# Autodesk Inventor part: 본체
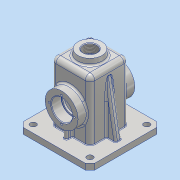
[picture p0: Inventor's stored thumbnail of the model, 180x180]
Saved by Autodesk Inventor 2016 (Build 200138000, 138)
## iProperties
Created: 2018-10
Part Number: 본체
Material: 알루미늄 6061
Document SubType Name: Modeling
Designer: user
Density: 2.7 g/cm^3
Appearance: 알루미늄 - 평지
Mass: 794.227 g
Surface Area: 899.5 cm^2
Volume: 294.158 cm^3
Author: user
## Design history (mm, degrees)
sketch "스케치1"
  geometry: L1 (-52, -60)-(52, -60); L2 (60, -52)-(60, 52); L3 (52, 60)-(-52, 60); L4 (-60, 52)-(-60, -52); L5 (-60, -60)-(60, 60); L6 (60, -60)-(-60, 60); L7 (-60, 52)-(-52, 60); L8 (52, 60)-(60, 52); L9 (60, -52)-(52, -60); L10 (-52, -60)-(-60, -52); 1 further point
  constraints: 20 end point, 8 point on line, 2 midpoint, 2 parallel, 1 horizontal, 1 perpendicular
  dimensions: "d0" = 120 distance of L5.start L6.start; "d1" = 120 distance of L5.end L6.start; "d2" = 8 distance of L4.start L6.end; "d3" = 8 distance of L3.end L6.end (= d2); "d4" = 8 distance of L3.start L5.end (= d2); "d5" = 8 distance of L2.end L5.end (= d4); "d6" = 8 distance of L2.start L6.start (= d2); "d7" = 8 distance of L1.end L6.start (= d6); "d8" = 8 distance of L1.start L5.start (= d2); "d9" = 8 distance of L4.end L5.start (= d8)
extrude "돌출1" new body sketch "스케치1" distance "d10" = 10; taper "d11" = 0 deg
sketch "스케치2"
  geometry: L1 (-32.5, 32.5)-(32.5, 32.5); L2 (32.5, 32.5)-(32.5, -32.5); L3 (32.5, -32.5)-(-32.5, -32.5); L4 (-32.5, -32.5)-(-32.5, 32.5); L5 (-32.5, 32.5)-(32.5, -32.5); L6 (32.5, 32.5)-(-32.5, -32.5); 1 further point
  constraints: 12 end point, 2 midpoint, 2 parallel, 1 horizontal, 1 perpendicular
  dimensions: "d12" = 65 distance of L1.start L1.end; "d13" = 65 distance of L1.end L2.end
extrude "돌출2" join sketch "스케치2" distance "d14" = 100; taper "d15" = 0 deg
node "작업 평면1"
fillet "모깎기1" dims "d17" = 8
fillet "모깎기2" dims "d18" = 8
feature "쉘1" dims "d19" = 10, "d20" = 5
sketch "스케치3"
  geometry: C1 r 20 at (0, 0); 1 further point
  constraints: 1 centre point, 1 coincident
  dimensions: "d21" = 40 diameter of C1
extrude "돌출3" join sketch "스케치3" stored distance "d22" = 100; taper "d23" = 7 deg
hole "구멍1" diameter "d26" = 22.835; stored, may be unused: countersink angle "d30" = 90 deg, drill point angle "d32" = 118 deg; dims "d24" = 10, "d25" = 10, "d27" = 50, "d28" = 4, "d29" = 2, "d31" = 59.3
sketch "스케치6"
  geometry: L1 (76.5, -10)-(-27.5, -10) reference; C1 r 27.5 at (24.5, 45); 2 further points
  constraints: 1 centre point, 1 midpoint, 1 vertical alignment
  dimensions: "d33" = 55 diameter of C1; "d34" = 55 distance from line of L1 C1.centre
extrude "돌출4" join sketch "스케치6" distance "d35" = 15; taper "d37" = 0 deg; dims "d36" = 2, "d38" = 0
hole "구멍2" diameter "d41" = 30; stored, may be unused: countersink angle "d45" = 90 deg, drill point angle "d47" = 118 deg; dims "d39" = 10, "d40" = 10, "d42" = 17, "d43" = 35, "d44" = 17, "d46" = 59.3
sketch "스케치7"
  geometry: C1 r 15 at (0, 0) reference; 2 further points
  constraints: 1 vertical alignment
  dimensions: "d48" = 21 distance of C1.centre point (0, 21)
hole "구멍3" sketch "스케치7" at (0, 21) diameter "d49" = 3.242; stored, may be unused: countersink angle "d53" = 90 deg, drill point angle "d55" = 118 deg; dims "d50" = 8, "d51" = 35, "d52" = 17, "d54" = 10
sketch "스케치8"
  geometry: L1 (-32.5, 27.5)-(-47.5, 27.5) reference; L2 (-42.5, 27.5)-(-42.5, 9.287); L3 (20, 120)-(21.228, 110) reference; L4 (21.228, 110)-(24.5, 110) reference; L5 (32.5, 102)-(32.5, 82.5) reference; L6 (32.5, 82.5)-(47.5, 82.5) reference; L7 (47.5, 82.5)-(47.5, 77.621) reference; L8 (47.5, 77.621)-(37.5, 77.621) reference; L9 (37.5, 77.621)-(36.526, 76) reference; L10 (36.526, 76)-(37.5, 74.379) reference; L11 (37.5, 74.379)-(47.5, 74.379) reference; L12 (47.5, 74.379)-(47.5, 72.5) reference; L13 (47.5, 72.5)-(30.5, 72.5) reference; L14 (30.5, 72.5)-(30.5, 70) reference; L15 (30.5, 70)-(27.5, 70) reference; L16 (27.5, 70)-(27.5, 102) reference; L17 (24.5, 105)-(11.418, 105) reference; L18 (11.418, 105)-(11.418, 120) reference; L19 (11.418, 120)-(20, 120) reference; L20 (-21.228, 110)-(-20, 120) reference; L21 (-20, 120)-(-11.418, 120) reference; L22 (-11.418, 120)-(-11.418, 105) reference; L23 (-11.418, 105)-(-24.5, 105) reference; L24 (-27.5, 102)-(-27.5, 70) reference; L25 (-27.5, 70)-(-30.5, 70) reference; L26 (-30.5, 70)-(-30.5, 72.5) reference; L27 (-30.5, 72.5)-(-47.5, 72.5) reference; L28 (-47.5, 72.5)-(-47.5, 74.379) reference; L29 (-47.5, 74.379)-(-37.5, 74.379) reference; L30 (-37.5, 74.379)-(-36.526, 76) reference; L31 (-36.526, 76)-(-37.5, 77.621) reference; L32 (-37.5, 77.621)-(-47.5, 77.621) reference; L33 (-47.5, 77.621)-(-47.5, 82.5) reference; L34 (-47.5, 82.5)-(-32.5, 82.5) reference; L35 (-32.5, 82.5)-(-32.5, 102) reference; L36 (-24.5, 110)-(-21.228, 110) reference; L37 (60, 10)-(60, 0) reference; L38 (60, 0)-(27.5, 0) reference; L39 (27.5, 0)-(27.5, 40) reference; L40 (27.5, 40)-(30.5, 40) reference; L41 (30.5, 40)-(30.5, 37.5) reference; L42 (30.5, 37.5)-(47.5, 37.5) reference; L43 (47.5, 37.5)-(47.5, 35.621) reference; L44 (47.5, 35.621)-(37.5, 35.621) reference; L45 (37.5, 35.621)-(36.526, 34) reference; L46 (36.526, 34)-(37.5, 32.379) reference; L47 (37.5, 32.379)-(47.5, 32.379) reference; L48 (47.5, 32.379)-(47.5, 27.5) reference; L49 (47.5, 27.5)-(32.5, 27.5) reference; L50 (32.5, 27.5)-(32.5, 10) reference; L51 (32.5, 10)-(60, 10) reference; L52 (-60, 0)-(-60, 10) reference; L53 (-60, 10)-(-32.5, 10) reference; L54 (-32.5, 10)-(-32.5, 27.5) reference; L55 (-32.5, 27.5)-(-47.5, 27.5) reference; L56 (-47.5, 27.5)-(-47.5, 32.379) reference; L57 (-47.5, 32.379)-(-37.5, 32.379) reference; L58 (-37.5, 32.379)-(-36.526, 34) reference; L59 (-36.526, 34)-(-37.5, 35.621) reference; L60 (-37.5, 35.621)-(-47.5, 35.621) reference; L61 (-47.5, 35.621)-(-47.5, 37.5) reference; L62 (-47.5, 37.5)-(-30.5, 37.5) reference; L63 (-30.5, 37.5)-(-30.5, 40) reference; L64 (-30.5, 40)-(-27.5, 40) reference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; A1 r 8 centre (24.5, 102) between (32.5, 102) and (24.5, 110) reference; A2 r 3 centre (24.5, 102) between (27.5, 102) and (24.5, 105) reference; A3 r 3 centre (-24.5, 102) between (-24.5, 105) and (-27.5, 102) reference; A4 r 8 centre (-24.5, 102) between (-24.5, 110) and (-32.5, 102) reference; 1 further point
  constraints: 2 end point, 1 point on line, 1 vertical
  dimensions: "d59" = 15 distance between parallel lines of L65 L2
feature "리브1" sketch "스케치8" dims "d60" = 1, "d61" = 6, "d62" = 0, "d63" = 0, "d64" = 1, "d65" = 1
sketch "스케치9"
  geometry: L1 (32.5, 102)-(32.5, 10) reference; L2 (60, 10)-(52, 10) reference; L3 (27.5, 0)-(27.5, 102) reference; L4 (24.5, 105)-(11.418, 105) reference; L5 (11.418, 105)-(11.418, 120) reference; L6 (11.418, 120)-(20, 120) reference; L7 (20, 120)-(21.228, 110) reference; L8 (21.228, 110)-(24.5, 110) reference; L9 (32.5, 102)-(32.5, 10) reference; L10 (32.5, 10)-(60, 10) reference; L11 (60, 10)-(60, 0) reference; L12 (60, 0)-(27.5, 0) reference; L13 (-27.5, 102)-(-27.5, 0) reference; L14 (-27.5, 0)-(-60, 0) reference; L15 (-60, 0)-(-60, 10) reference; L16 (-60, 10)-(-32.5, 10) reference; L17 (-32.5, 10)-(-32.5, 102) reference; L18 (-24.5, 110)-(-21.228, 110) reference; L19 (-21.228, 110)-(-20, 120) reference; L20 (-20, 120)-(-11.418, 120) reference; L21 (-11.418, 120)-(-11.418, 105) reference; L22 (-11.418, 105)-(-24.5, 105) reference; L23 (32.5, 10)-(32.5, 102) reference; L24 (32.5, 97.905)-(48, 10); A1 r 3 centre (24.5, 102) between (27.5, 102) and (24.5, 105) reference; A2 r 8 centre (24.5, 102) between (32.5, 102) and (24.5, 110) reference; A3 r 8 centre (-24.5, 102) between (-24.5, 110) and (-32.5, 102) reference; A4 r 3 centre (-24.5, 102) between (-24.5, 105) and (-27.5, 102) reference; 1 further point
  constraints: 2 end point, 2 point on line
  dimensions: "d66" = 12 distance from line of L11 L24.end; "d67" = 10 deg angle of L11 L24
feature "리브2" sketch "스케치9" dims "d68" = 1, "d69" = 10, "d70" = 0, "d71" = 0, "d72" = 1, "d73" = 1
fillet "모깎기3" dims "d74" = 0.3
sketch "스케치10"
  geometry: L1 (47.5, -47.5)-(47.5, 47.5); L2 (47.5, 47.5)-(-47.5, 47.5); L3 (-47.5, 47.5)-(-47.5, -47.5); L4 (-47.5, -47.5)-(47.5, -47.5); L5 (47.5, -47.5)-(-47.5, 47.5); L6 (47.5, 47.5)-(-47.5, -47.5); 5 further points
  constraints: 12 end point, 4 coincident, 2 midpoint, 2 parallel, 1 perpendicular, 1 vertical
  dimensions: "d75" = 95 distance of L1.start L1.end; "d76" = 95 distance of L2.end L1.end
hole "구멍4" sketch "스케치10" at (-47.5, -47.5), (-47.5, 47.5), (47.5, 47.5), (47.5, -47.5) diameter "d77" = 10; stored, may be unused: countersink angle "d81" = 90 deg, drill point angle "d83" = 118 deg; dims "d78" = 8, "d79" = 35, "d80" = 17, "d82" = 10
fillet "모깎기4" dims "d84" = 3
fillet "모깎기5" dims "d85" = 3
fillet "모깎기6" dims "d86" = 3
fillet "모깎기7" dims "d87" = 3
fillet "모깎기8" dims "d88" = 1
chamfer "모따기1" distance "d89" = 1; stored, may be unused: second distance "d90" = 2, angle "d91" = 45 deg
sketch "스케치11"
  geometry: L1 (57, 0)-(57, 91) reference; L2 (44.5, -18)-(4.5, -18) reference; 2 further points
  constraints: 1 other
  dimensions: "d92" = 32.5 distance from line of L1 point (24.5, 8); "d93" = 26 distance from line of L2 point (24.5, 8)
feature "엠보싱1" sketch "스케치11" dims "d0" = 120, "d1" = 120, "d2" = 8, "d3" = 8 (= d2), "d4" = 8 (= d2), "d5" = 8 (= d4), "d6" = 8 (= d2), "d7" = 8 (= d6), "d8" = 8 (= d2), "d9" = 8 (= d8), "d94" = 0.5, "d95" = 0
node "솔리드1"
pattern_circular "원형 패턴1" dims angle "d57" = 360 deg
mirror "대칭1"
mirror "대칭2"
mirror "대칭3"
node "작업 평면2"
node "작업 평면3"
node "절단 모서리 투영1"
node "절단 모서리 투영2"
